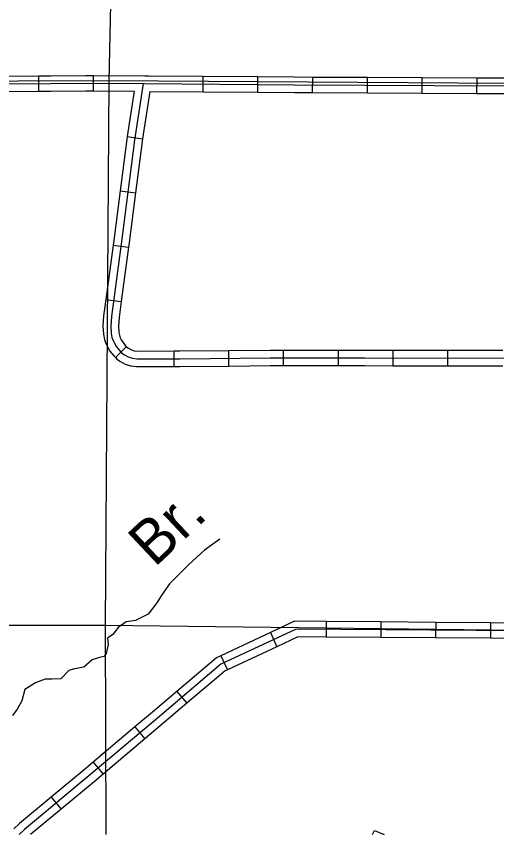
# Model space of a CAD drawing. Extents: x -492261 to -432772, y 1441225 to 1452922.
# Drawn here: x -458422.6 to -458290.4, y 1450742 to 1450967.5 of the extents above; entities that cross this region are included whole.
import ezdxf

# ---------------------------------------------------------------- set-up
doc = ezdxf.new("R2010")
doc.units = 0
doc.layers.add('Default', color=7, linetype='Continuous')

msp = doc.modelspace()

# ---------------------------------------------------------------- linework, layer by layer
at = {"layer": 'Default'}
for p, q in [((-458416.46, 1450946.87), (-458416.48, 1450951.16)), ((-458401.4, 1450946.97), (-458401.37, 1450951.26)), ((-458371.23, 1450946.75), (-458371.2, 1450951.03)), ((-458356.15, 1450946.63), (-458356.11, 1450950.92)), ((-458341.06, 1450946.53), (-458341.03, 1450950.81)), ((-458325.97, 1450946.45), (-458325.95, 1450950.74)), ((-458310.88, 1450946.38), (-458310.86, 1450950.66)), ((-458295.8, 1450946.3), (-458295.78, 1450950.59)), ((-458392.13, 1450934.44), (-458387.9, 1450933.78)), ((-458394.08, 1450919.43), (-458389.83, 1450918.88)), ((-458396, 1450904.47), (-458391.76, 1450903.91)), ((-458397.99, 1450889.52), (-458393.75, 1450888.95)), ((-458395.35, 1450873.46), (-458392.31, 1450876.49)), ((-458379.21, 1450871.01), (-458379.22, 1450875.29)), ((-458364.11, 1450871.15), (-458364.15, 1450875.43)), ((-458349.04, 1450871.26), (-458349.04, 1450875.55)), ((-458333.96, 1450871.26), (-458333.96, 1450875.55)), ((-458318.88, 1450871.24), (-458318.87, 1450875.53)), ((-458303.79, 1450871.21), (-458303.78, 1450875.5)), ((-458337.32, 1450800.71), (-458337.35, 1450796.43)), ((-458322.24, 1450800.6), (-458322.27, 1450796.32)), ((-458307.15, 1450800.49), (-458307.18, 1450796.21)), ((-458292.07, 1450800.38), (-458292.1, 1450796.1)), ((-458352.69, 1450797.67), (-458350.87, 1450793.78)), ((-458366.35, 1450791.28), (-458364.54, 1450787.4)), ((-458378.48, 1450781.43), (-458375.71, 1450778.17)), ((-458389.98, 1450771.68), (-458387.22, 1450768.41)), ((-458401.5, 1450761.93), (-458398.73, 1450758.66)), ((-458413.06, 1450752.27), (-458410.32, 1450748.98)), ((-458324.53, 1450741.98), (-458324.01, 1450743.15))]:
    msp.add_line(p, q, dxfattribs=at)
for points in [[(-458393.96, 1451097.46), (-458397.16, 1450949.72), (-458398.2, 1450799.72), (-458398.04, 1450741.98)], [(-457944.16, 1450953.01), (-458096.23, 1450948.31), (-458246.26, 1450948.79), (-458397.16, 1450949.72), (-458547.12, 1450949.17), (-458698.3, 1450950.04), (-458721.58, 1450950.06)], [(-458431.57, 1450951.07), (-458416.48, 1450951.16)], [(-458416.48, 1450951.16), (-458413.14, 1450951.18), (-458403.49, 1450951.27), (-458401.37, 1450951.26)], [(-458401.37, 1450951.26), (-458387.28, 1450951.16), (-458386.28, 1450951.15)], [(-458386.28, 1450951.15), (-458371.2, 1450951.03)], [(-458371.2, 1450951.03), (-458356.11, 1450950.92)], [(-458356.11, 1450950.92), (-458346.01, 1450950.84), (-458341.03, 1450950.81)], [(-458341.03, 1450950.81), (-458325.95, 1450950.74)], [(-458325.95, 1450950.74), (-458310.86, 1450950.66)], [(-458310.86, 1450950.66), (-458295.78, 1450950.59)], [(-458295.78, 1450950.59), (-458288.3, 1450950.55), (-458280.69, 1450950.51)], [(-458491.9, 1450948.57), (-458413.12, 1450949.04), (-458403.49, 1450949.13), (-458387.3, 1450949.02), (-458346.02, 1450948.69), (-458288.31, 1450948.41), (-458246.66, 1450948.21), (-458213.4, 1450948.2), (-458171.58, 1450947.84)], [(-458387.7, 1450949.02), (-458390.13, 1450933.36), (-458393.71, 1450905.44), (-458396.46, 1450884.76), (-458396.64, 1450882.17), (-458396.53, 1450880.18), (-458396.32, 1450879.04), (-458396, 1450878.15), (-458395.66, 1450877.41), (-458395.1, 1450876.45), (-458394.15, 1450875.3), (-458393.57, 1450874.71), (-458392.82, 1450874.22), (-458391.81, 1450873.68), (-458390.67, 1450873.29), (-458389.44, 1450873.11), (-458377.57, 1450873.16), (-458352.74, 1450873.41), (-458326.65, 1450873.4), (-458300.22, 1450873.35), (-458271.72, 1450873.4)], [(-458431.54, 1450946.78), (-458416.46, 1450946.87)], [(-458416.46, 1450946.87), (-458413.11, 1450946.89), (-458403.48, 1450946.99), (-458401.4, 1450946.97)], [(-458401.4, 1450946.97), (-458390.2, 1450946.89)], [(-458390.2, 1450946.89), (-458392.13, 1450934.44)], [(-458385.86, 1450946.86), (-458387.9, 1450933.78)], [(-458385.86, 1450946.86), (-458371.23, 1450946.75)], [(-458371.23, 1450946.75), (-458356.15, 1450946.63)], [(-458356.15, 1450946.63), (-458346.04, 1450946.55), (-458341.06, 1450946.53)], [(-458341.06, 1450946.53), (-458325.97, 1450946.45)], [(-458325.97, 1450946.45), (-458310.88, 1450946.38)], [(-458310.88, 1450946.38), (-458295.8, 1450946.3)], [(-458295.8, 1450946.3), (-458288.32, 1450946.26), (-458280.71, 1450946.23)], [(-458392.13, 1450934.44), (-458392.25, 1450933.66), (-458394.08, 1450919.43)], [(-458387.9, 1450933.78), (-458388.01, 1450933.06), (-458389.83, 1450918.88)], [(-458394.08, 1450919.43), (-458395.84, 1450905.72), (-458396, 1450904.47)], [(-458389.83, 1450918.88), (-458391.59, 1450905.16), (-458391.76, 1450903.91)], [(-458396, 1450904.47), (-458397.99, 1450889.52)], [(-458391.76, 1450903.91), (-458393.75, 1450888.95)], [(-458397.99, 1450889.52), (-458398.6, 1450884.98), (-458398.79, 1450882.19), (-458398.66, 1450879.92), (-458398.39, 1450878.48), (-458397.98, 1450877.35), (-458397.57, 1450876.43), (-458396.86, 1450875.23), (-458395.75, 1450873.86), (-458395.35, 1450873.46)], [(-458393.75, 1450888.95), (-458394.33, 1450884.55), (-458394.49, 1450882.16), (-458394.4, 1450880.43), (-458394.24, 1450879.61), (-458394.01, 1450878.96), (-458393.76, 1450878.4), (-458393.33, 1450877.68), (-458392.56, 1450876.73), (-458392.31, 1450876.49)], [(-458392.31, 1450876.49), (-458392.21, 1450876.38), (-458391.72, 1450876.06), (-458390.95, 1450875.65), (-458390.17, 1450875.38), (-458389.3, 1450875.26), (-458379.22, 1450875.29)], [(-458379.22, 1450875.29), (-458377.58, 1450875.3), (-458364.15, 1450875.43)], [(-458364.15, 1450875.43), (-458352.75, 1450875.55), (-458349.04, 1450875.55)], [(-458349.04, 1450875.55), (-458333.96, 1450875.55)], [(-458333.96, 1450875.55), (-458326.65, 1450875.54), (-458318.87, 1450875.53)], [(-458318.87, 1450875.53), (-458303.78, 1450875.5)], [(-458303.78, 1450875.5), (-458300.22, 1450875.49), (-458288.7, 1450875.51)], [(-458395.35, 1450873.46), (-458394.93, 1450873.04), (-458393.92, 1450872.37), (-458392.67, 1450871.7), (-458391.17, 1450871.19), (-458389.59, 1450870.97), (-458379.21, 1450871.01)], [(-458364.11, 1450871.15), (-458352.73, 1450871.26), (-458349.04, 1450871.26)], [(-458349.04, 1450871.26), (-458333.96, 1450871.26)], [(-458333.96, 1450871.26), (-458326.65, 1450871.26), (-458318.88, 1450871.24)], [(-458318.88, 1450871.24), (-458303.79, 1450871.21)], [(-458379.21, 1450871.01), (-458377.55, 1450871.01), (-458364.11, 1450871.15)], [(-458303.79, 1450871.21), (-458300.22, 1450871.2), (-458288.7, 1450871.22)], [(-458366.61, 1450823.42), (-458370.83, 1450820.38), (-458375.21, 1450816.33), (-458380.44, 1450811.1), (-458382.8, 1450807.84), (-458383.92, 1450805.89), (-458386.36, 1450802.72), (-458389.87, 1450800.97), (-458392.38, 1450800.66), (-458394.61, 1450799.03), (-458396.11, 1450797.13), (-458397.54, 1450796.09), (-458397.39, 1450794.38), (-458397.9, 1450791.9), (-458398.48, 1450791.11), (-458399.79, 1450790.82), (-458401.75, 1450790.12), (-458404.08, 1450788.18), (-458406.59, 1450787.69), (-458408.21, 1450787.25), (-458410.39, 1450784.96), (-458412.79, 1450784.82), (-458414.7, 1450784.86), (-458417.4, 1450783.8), (-458420.27, 1450781.99), (-458421.14, 1450778.84), (-458422.38, 1450776.55), (-458423.68, 1450774.77)], [(-458745.84, 1450800.3), (-458699.18, 1450800.33), (-458547.83, 1450799.69), (-458398.2, 1450799.72), (-458246.15, 1450797.9), (-458095.56, 1450797.76), (-457945.04, 1450799.46)], [(-458337.32, 1450800.71), (-458346.03, 1450800.78), (-458352.69, 1450797.67)], [(-458322.24, 1450800.6), (-458337.32, 1450800.71)], [(-458307.15, 1450800.49), (-458322.24, 1450800.6)], [(-458292.07, 1450800.38), (-458307.15, 1450800.49)], [(-458276.98, 1450800.27), (-458292.07, 1450800.38)], [(-458171.4, 1450797.57), (-458246.65, 1450797.91), (-458345.56, 1450798.63), (-458366.34, 1450788.92), (-458383.25, 1450774.57), (-458402.64, 1450758.16), (-458420.37, 1450743.39), (-458421.91, 1450741.98), (-458421.91, 1450741.98)], [(-458352.69, 1450797.67), (-458366.35, 1450791.28)], [(-458337.35, 1450796.43), (-458345.09, 1450796.48), (-458350.87, 1450793.78)], [(-458322.27, 1450796.32), (-458337.35, 1450796.43)], [(-458307.18, 1450796.21), (-458322.27, 1450796.32)], [(-458292.1, 1450796.1), (-458307.18, 1450796.21)], [(-458277.01, 1450795.99), (-458292.1, 1450796.1)], [(-458350.87, 1450793.78), (-458364.54, 1450787.4)], [(-458366.35, 1450791.28), (-458367.5, 1450790.74), (-458378.48, 1450781.43)], [(-458364.54, 1450787.4), (-458365.17, 1450787.1), (-458375.71, 1450778.17)], [(-458378.48, 1450781.43), (-458384.64, 1450776.21), (-458389.98, 1450771.68)], [(-458375.71, 1450778.17), (-458381.87, 1450772.94), (-458387.22, 1450768.41)], [(-458389.98, 1450771.68), (-458401.5, 1450761.93)], [(-458387.22, 1450768.41), (-458398.73, 1450758.66)], [(-458401.5, 1450761.93), (-458404.01, 1450759.8), (-458413.06, 1450752.27)], [(-458398.73, 1450758.66), (-458401.26, 1450756.52), (-458410.32, 1450748.98)], [(-458413.06, 1450752.27), (-458421.78, 1450745.01), (-458423.36, 1450743.56)], [(-458410.32, 1450748.98), (-458418.73, 1450741.98)], [(-458324.01, 1450743.15), (-458321.39, 1450741.98)]]:
    msp.add_lwpolyline(points, dxfattribs=at)

# ---------------------------------------------------------------- texts
msp.add_text('Br.', height=12.069, rotation=43.2142, dxfattribs=at).set_placement((-458384.61, 1450815.44))

doc.saveas('drawing.dxf')
